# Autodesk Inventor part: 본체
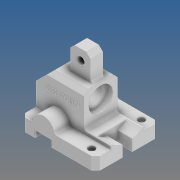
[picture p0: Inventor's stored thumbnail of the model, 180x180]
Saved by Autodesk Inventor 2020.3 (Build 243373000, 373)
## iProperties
Created: 2022-08
Part Number: 본체
Material: 알루미늄 6061
Document SubType Name: Modeling
Designer: EZDESIGN
Density: 2.7 g/cm^3
Appearance: 기본값
Mass: 499.243 g
Surface Area: 337.564 cm^2
Volume: 184.905 cm^3
Author: EZDESIGN
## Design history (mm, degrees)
sketch "스케치1"
  geometry: L1 (0, 15)-(90, 15); L2 (90, 15)-(90, 0); L3 (90, 0)-(0, 0); L4 (0, 0)-(0, 15); C1 r 13 at (27, 15); 3 further points
  constraints: 8 end point, 2 parallel, 1 centre point, 1 coincident, 1 horizontal, 1 perpendicular, 1 point on line
  dimensions: "d0" = 15 distance of L3.end L1.start; "d1" = 90 distance of L2.end L3.end; "d18" = 26 diameter of C1; "d19" = 27 distance from line of L4 C1.centre
extrude "돌출1" new body sketch "스케치1" distance "d4" = 18; taper "d5" = 0 deg
sketch "스케치2"
  geometry: L1 (0, 15)-(0, 0) reference; L2 (0, 15)-(0, 42); L3 (0, 42)-(-18, 60); L4 (-18, 60)-(-58, 60); L5 (-58, 60)-(-58, 19); L6 (-58, 19)-(-90, 19); L7 (-90, 19)-(-90, 15); L8 (-90, 0)-(-90, 15) reference; L9 (-90, 15)-(0, 15) reference; L10 (0, 0)-(-90, 0) reference; 1 further point
  constraints: 12 end point, 4 perpendicular, 1 collinear, 1 vertical
  dimensions: "d7" = 45 distance between parallel lines of L9 L4; "d8" = 45 deg angle of L3 L2; "d9" = 18 horizontal distance of L2.end L3.end; "d10" = 32 distance between parallel lines of L7 L5; "d11" = 19 distance between parallel lines of L10 L6
extrude "돌출2" join sketch "스케치2" distance "d12" = 40; taper "d13" = 0 deg
fillet "모깎기2" dims "d14" = 3
chamfer "모따기1" distance "d15" = 5; stored, may be unused: second distance "d16" = 2, angle "d17" = 45 deg
fillet "모깎기3" dims "d20" = 3
node "작업 평면1"
sketch "스케치5"
  geometry: L1 (58, 42)-(0, 42); L2 (0, 0)-(90, 0) reference; L3 (58, 55)-(58, 22) reference; L4 (0, 15)-(0, 42) reference; L5 (58, 42)-(58, 56.5); L6 (51, 56.5)-(51, 53); L7 (50, 52)-(0, 52); L8 (0, 52)-(0, 42); L9 (58, 56.5)-(51, 56.5); L10 (51, 53)-(50, 52); 3 further points
  constraints: 14 end point, 5 point on line, 2 horizontal, 2 perpendicular, 1 vertical
  dimensions: "d31" = 42 distance between parallel lines of L2 L1; "d32" = 29 diameter of L9 L1; "d33" = 20 diameter of L7 L1; "d34" = 7 distance of L5.end L6.start; "d35" = 1 distance of L6.end point (51, 52); "d36" = 1 distance of L7.start point (51, 52) (= d35)
revolve "회전1" sketch "스케치5" stored, may be unused: angle "d37" = 90 deg
sketch "스케치6"
  geometry: L1 (18, 19)-(58, 19) reference; L2 (32, 13.627)-(44, 13.627); L3 (44, 13.627)-(44, 0); L4 (44, 0)-(32, 0); L5 (32, 0)-(32, 13.627); L6 (0, 0)-(76, 0) reference; L7 (20.336, 19)-(55.664, 19); C1 r 14.5 at (38, 42) reference; A1 r 29 centre (38, 42) between (55.664, 19) and (20.336, 19); A2 r 29 centre (38, 42) between (20.336, 19) and (32, 13.627); A3 r 29 centre (38, 42) between (44, 13.627) and (55.664, 19); A4 r 29 centre (38, 42) between (32, 13.627) and (44, 13.627); 1 further point
  constraints: 10 end point, 9 point on circle, 4 centre point, 2 collinear, 2 parallel, 2 point on line, 1 coincident, 1 horizontal, 1 midpoint, 1 perpendicular, 1 vertical alignment
  dimensions: "d38" = 58 diameter of A1; "d39" = 12 distance of L3.end L4.end
extrude "돌출5" cut sketch "스케치6" distance "d40" = 18; taper "d41" = 0 deg
sketch "스케치7"
  geometry: L1 (58, 60)-(18, 60) reference; L2 (29, 60)-(29, 90); L3 (29, 90)-(53, 90); L4 (53, 90)-(53, 60); L5 (58, 55)-(58, 22) reference; 1 further point
  constraints: 6 end point, 2 point on line, 1 horizontal, 1 perpendicular, 1 vertical
  dimensions: "d42" = 24 distance of L2.end L3.end; "d43" = 5 distance between parallel lines of L5 L4; "d44" = 30 distance of L3.end L4.end
extrude "돌출6" join sketch "스케치7" stored distance "d45" = 15; taper "d46" = 0 deg
fillet "모깎기4" dims "d47" = 3
chamfer "모따기2" distance "d48" = 5; stored, may be unused: second distance "d49" = 2, angle "d50" = 45 deg
sketch "스케치8"
  geometry: L1 (53, 63)-(53, 85) reference; L2 (0, 0)-(90, 0) reference; 2 further points
  dimensions: "d58" = 12 distance from line of L1 point (41, 77); "d59" = 77 distance from line of L2 point (41, 77)
hole "구멍1" sketch "스케치8" at (41, 77) diameter "d51" = 8; stored, may be unused: countersink angle "d55" = 90 deg, drill point angle "d57" = 118 deg; dims "d52" = 6, "d53" = 4, "d54" = 2, "d56" = 8
chamfer "모따기3" distance "d60" = 1; stored, may be unused: second distance "d61" = 2, angle "d62" = 45 deg
sketch "스케치9"
  geometry: L1 (47.284, 0)-(47.284, -18) reference; L2 (47.284, 0)-(0, 0) reference; 2 further points
  dimensions: "d70" = 13 distance from line of L1 point (34.284, -8); "d71" = 8 distance from line of L2 point (34.284, -8)
hole "구멍2" sketch "스케치9" at (34.284, -8) diameter "d63" = 4.5; stored, may be unused: countersink angle "d67" = 90 deg, drill point angle "d69" = 118 deg; dims "d64" = 6, "d65" = 8, "d66" = 4.4, "d68" = 8
sketch "스케치10"
  geometry: L1 (58, 55)-(58, 22) reference; L2 (58, 60)-(18, 60) reference; 2 further points
  constraints: 1 other
  dimensions: "d75" = 26 distance from line of L1 point (32, 42); "d76" = 18 distance from line of point (32, 42) L2
feature "엠보싱1" sketch "스케치10" dims "d0" = 15, "d1" = 90, "d18" = 26, "d19" = 27, "d77" = 0.5, "d78" = 0
sketch "스케치4"
  geometry: L1 (17, 8)-(37, 8); L2 (37, 8)-(37, 0); L3 (37, 0)-(17, 0); L4 (17, 0)-(17, 8); L5 (0, 0)-(90, 0) reference; A1 r 13 centre (27, 15) between (39.769, 17.438) and (14.231, 17.438) reference; 1 further point
  constraints: 8 end point, 2 parallel, 1 collinear, 1 horizontal, 1 midpoint, 1 perpendicular, 1 vertical alignment
  dimensions: "d26" = 20 distance of L1.start L1.end; "d27" = 8 distance of L1.end L2.end
extrude "돌출7" cut sketch "스케치4" extent not by distance; stored distance "d79" = 0; taper "d80" = 0 deg
chamfer "모따기4" distance "d81" = 5; stored, may be unused: second distance "d82" = 2, angle "d83" = 45 deg
node "솔리드1"
mirror "미러1"
pattern_linear "직사각형 패턴1" dims "d74" = 60
feature "A9D066F2-1C7D-4E18-AEED-F7BC21143FA4" dims "d63" = 4.5, "d64" = 6, "d65" = 8, "d66" = 4.4, "d67" = 90 deg, "d68" = 8, "d69" = 118 deg
other parameters: "d30" = -38
